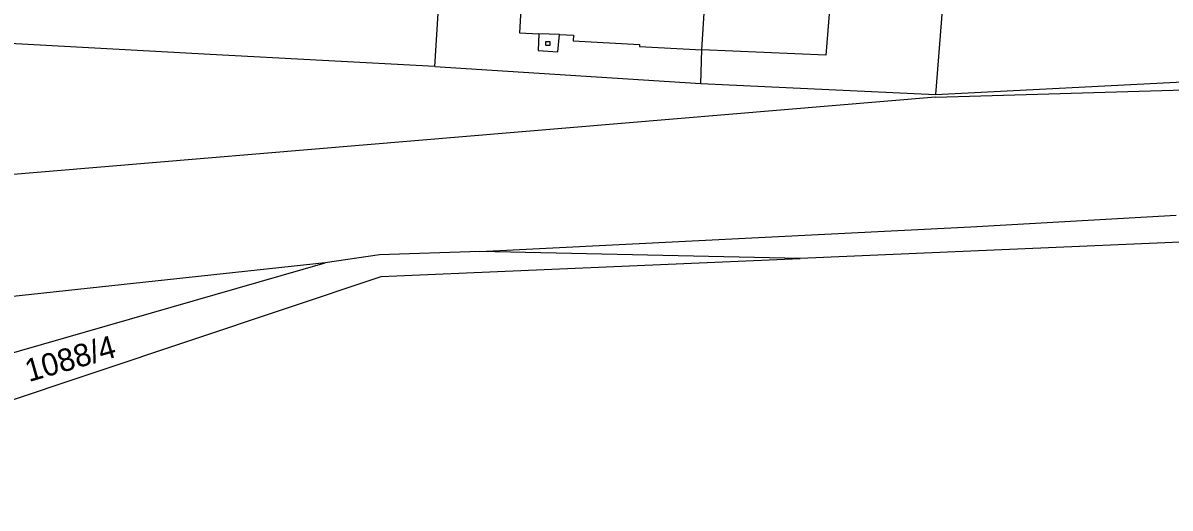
# Model space of a CAD drawing. Extents: x -711879 to -711361, y -1048782 to -1048177.
# Drawn here: x -711571.3 to -711485, y -1048409 to -1048372.4 of the extents above; entities that cross this region are included whole.
import ezdxf

# ---------------------------------------------------------------- set-up
doc = ezdxf.new("R2010")
doc.units = 0
for name, color, linetype in [('Vrstva 1', 7, 'Continuous'), ('Vrstva 14', 7, 'Continuous'), ('Vrstva 2', 7, 'Continuous'), ('Vrstva 25', 7, 'Continuous'), ('Vrstva 46', 7, 'Continuous')]:
    doc.layers.add(name, color=color, linetype=linetype)

msp = doc.modelspace()

# ---------------------------------------------------------------- linework, layer by layer
at = {"layer": 'Vrstva 1'}
for p, q in [((-711500.73, -1048353.71), (-711502.65, -1048377.83)), ((-711540.33, -1048375.71), (-711539.49, -1048361.89)), ((-711533.47, -1048364.37), (-711533.97, -1048373.17)), ((-711520.23, -1048374.45), (-711519.75, -1048366.23)), ((-711557.26, -1048374.8), (-711581.05, -1048373.49)), ((-711533.97, -1048373.17), (-711532.5, -1048373.24)), ((-711532.5, -1048373.24), (-711532.57, -1048374.51)), ((-711531.07, -1048374.61), (-711530.95, -1048373.31)), ((-711530.95, -1048373.31), (-711529.91, -1048373.36)), ((-711529.91, -1048373.36), (-711529.92, -1048373.78)), ((-711529.92, -1048373.78), (-711524.93, -1048374.06)), ((-711532.57, -1048374.51), (-711531.07, -1048374.61)), ((-711524.93, -1048374.06), (-711524.94, -1048374.21)), ((-711524.94, -1048374.21), (-711520.23, -1048374.45)), ((-711520.33, -1048376.99), (-711520.23, -1048374.45)), ((-711540.33, -1048375.71), (-711557.26, -1048374.8)), ((-711540.33, -1048375.71), (-711520.33, -1048376.99)), ((-711502.65, -1048377.83), (-711469.67, -1048376.1)), ((-711520.33, -1048376.99), (-711502.65, -1048377.83)), ((-711502.66, -1048378.02), (-711469.7, -1048377.03)), ((-711502.66, -1048378.02), (-711580.18, -1048384.52)), ((-711398.19, -1048385.23), (-711512.84, -1048390.16)), ((-711500, -1048387.78), (-711484.54, -1048386.9)), ((-711536.95, -1048389.63), (-711500, -1048387.78)), ((-711544.51, -1048389.89), (-711548.59, -1048390.49)), ((-711536.95, -1048389.63), (-711544.51, -1048389.89)), ((-711544.38, -1048391.51), (-711512.84, -1048390.16)), ((-711512.84, -1048390.16), (-711536.95, -1048389.63)), ((-711548.59, -1048390.49), (-711579.07, -1048393.79)), ((-711574.28, -1048397.89), (-711548.59, -1048390.49)), ((-711596.54, -1048408.95), (-711544.38, -1048391.51))]:
    msp.add_line(p, q, dxfattribs=at)
at = {"layer": 'Vrstva 2'}
for p, q in [((-711510.23, -1048366.72), (-711510.91, -1048374.85)), ((-711530.95, -1048373.31), (-711532.5, -1048373.24)), ((-711510.91, -1048374.85), (-711520.23, -1048374.45))]:
    msp.add_line(p, q, dxfattribs=at)
at = {"layer": 'Vrstva 25'}
for p, q in [((-711531.98, -1048373.83), (-711531.68, -1048373.83)), ((-711531.98, -1048374.13), (-711531.98, -1048373.83)), ((-711531.68, -1048374.13), (-711531.98, -1048374.13)), ((-711531.68, -1048373.83), (-711531.68, -1048374.13))]:
    msp.add_line(p, q, dxfattribs=at)
at = {"layer": 'Vrstva 46'}
for p, q in [((-711529.92, -1048373.78), (-711529.92, -1048373.78)), ((-711529.91, -1048373.36), (-711529.91, -1048373.36)), ((-711524.94, -1048374.21), (-711524.94, -1048374.21)), ((-711524.93, -1048374.06), (-711524.93, -1048374.06)), ((-711520.23, -1048374.45), (-711520.23, -1048374.45)), ((-711510.91, -1048374.85), (-711510.91, -1048374.85)), ((-711540.33, -1048375.71), (-711540.33, -1048375.71)), ((-711520.33, -1048376.99), (-711520.33, -1048376.99)), ((-711502.65, -1048377.83), (-711502.65, -1048377.83))]:
    msp.add_line(p, q, dxfattribs=at)

# ---------------------------------------------------------------- texts
at = {"layer": 'Vrstva 14'}
msp.add_text('1088/4', height=1.7, rotation=16.0524, dxfattribs=at).set_placement((-711570.9, -1048399.47))

doc.saveas('drawing.dxf')
